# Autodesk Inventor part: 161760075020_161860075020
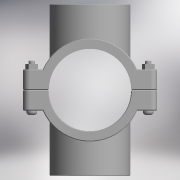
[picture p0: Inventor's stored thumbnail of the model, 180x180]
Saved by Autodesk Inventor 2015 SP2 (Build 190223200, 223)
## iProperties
Created: 2017-05
Part Number: 161760075020_161860075020
Material: Generic
Description: PLASSON DOUBLE SADDLE 75-2"
Document SubType Name: Modeling
Designer: KIM
Density: 1 g/cm^3
Appearance: Default
Author: KIM
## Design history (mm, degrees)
derived "16176.ipt"
feature "Solid1::16176.ipt"
feature "Solid2::16176.ipt"
tag "TaggingFeature1"
body "Solid1"
body "Solid2"
other parameters: "d0" = 93.75, "d1" = 122, "d2" = 37.5, "d3" = 75, "d4" = 98, "d5" = 0, "d6" = 6.1, "d7" = 122, "d8" = 0.1, "d10" = 0, "d11" = 0.75, "d20" = 0.75, "d23" = 0.75, "d37" = 8, "d38" = 45.5, "d39" = 0, "d40" = 3, "d41" = 5, "d42" = 0, "d43" = 6, "d44" = 3, "d45" = 0, "d46" = 0.75, "d52" = 56.656, "d54" = 0, "d57" = 0, "d58" = 81, "d60" = 0, "d63" = 8, "d66" = 82, "d67" = 156, "d68" = 73.6528, "d69" = 56.656, "d71" = 0, "d74" = 0, "d75" = 0.75, "d_" = 75, "G_" = 56.656, "A_" = 78, "L_" = 122, "L_1" = 98
